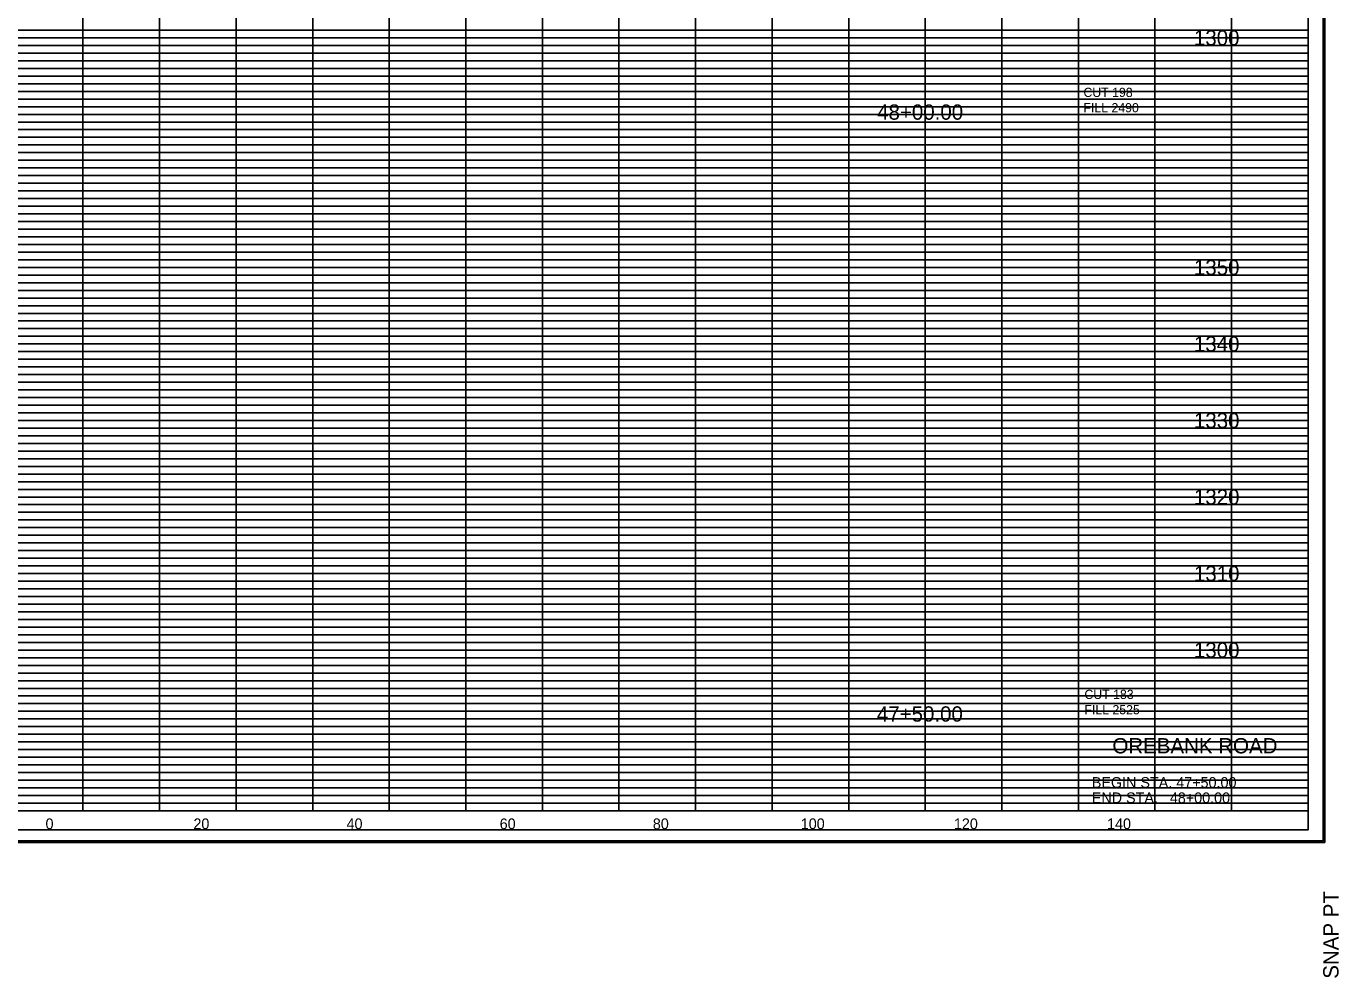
# Model space of a CAD drawing. Extents: x 980 to 1324, y 978 to 2847.
# Drawn here: x 1152.6 to 1324, y 2328.2 to 2452.5 of the extents above; entities that cross this region are included whole.
import ezdxf

# ---------------------------------------------------------------- set-up
doc = ezdxf.new("R2010")
doc.units = 0
for name, color, linetype in [('DESIGN - SHEET - Corner Text', 7, 'Continuous'), ('DESIGN - SHEET - Light Grid', 7, 'Continuous'), ('DESIGN - SHEET - Linework', 7, 'Continuous'), ('DESIGN - SHEET - Plot Shape', 7, 'Continuous'), ('DESIGN - TYPICAL - Text', 7, 'Continuous')]:
    doc.layers.add(name, color=color, linetype=linetype)

# ---------------------------------------------------------------- blocks, each defined once
blk = doc.blocks.new('XSTSHT')
at = {"layer": 'DESIGN - SHEET - Light Grid'}
for p, q in [((8, 10.2), (16, 10.2)), ((16, 10.2), (24, 10.2)), ((24, 10.2), (32, 10.2)), ((8, 10.1), (16, 10.1)), ((16, 10.1), (24, 10.1)), ((24, 10.1), (32, 10.1)), ((8, 9.9), (16, 9.9)), ((8, 9.8), (16, 9.8)), ((16, 9.9), (24, 9.9)), ((16, 9.8), (24, 9.8)), ((24, 9.9), (32, 9.9)), ((24, 9.8), (32, 9.8)), ((8, 9.7), (16, 9.7)), ((8, 9.6), (16, 9.6)), ((16, 9.7), (24, 9.7)), ((16, 9.6), (24, 9.6)), ((24, 9.7), (32, 9.7)), ((24, 9.6), (32, 9.6)), ((8, 9.5), (16, 9.5)), ((16, 9.5), (24, 9.5)), ((24, 9.5), (32, 9.5)), ((8, 9.4), (16, 9.4)), ((8, 9.3), (16, 9.3)), ((16, 9.4), (24, 9.4)), ((16, 9.3), (24, 9.3)), ((24, 9.4), (32, 9.4)), ((24, 9.3), (32, 9.3)), ((8, 9.2), (16, 9.2)), ((8, 9.1), (16, 9.1)), ((16, 9.2), (24, 9.2)), ((16, 9.1), (24, 9.1)), ((24, 9.2), (32, 9.2)), ((24, 9.1), (32, 9.1)), ((8, 8.9), (16, 8.9)), ((8, 8.8), (16, 8.8)), ((16, 8.9), (24, 8.9)), ((16, 8.8), (24, 8.8)), ((24, 8.9), (32, 8.9)), ((24, 8.8), (32, 8.8)), ((8, 8.7), (16, 8.7)), ((8, 8.6), (16, 8.6)), ((16, 8.7), (24, 8.7)), ((16, 8.6), (24, 8.6)), ((24, 8.7), (32, 8.7)), ((24, 8.6), (32, 8.6)), ((8, 8.5), (16, 8.5)), ((8, 8.4), (16, 8.4)), ((16, 8.5), (24, 8.5)), ((16, 8.4), (24, 8.4)), ((24, 8.5), (32, 8.5)), ((24, 8.4), (32, 8.4)), ((8, 8.3), (16, 8.3)), ((16, 8.3), (24, 8.3)), ((24, 8.3), (32, 8.3)), ((8, 8.2), (16, 8.2)), ((8, 8.1), (16, 8.1)), ((16, 8.2), (24, 8.2)), ((16, 8.1), (24, 8.1)), ((24, 8.2), (32, 8.2)), ((24, 8.1), (32, 8.1)), ((8, 7.9), (16, 7.9)), ((16, 7.9), (24, 7.9)), ((24, 7.9), (32, 7.9)), ((8, 7.8), (16, 7.8)), ((16, 7.8), (24, 7.8)), ((24, 7.8), (32, 7.8)), ((8, 7.7), (16, 7.7)), ((8, 7.6), (16, 7.6)), ((16, 7.7), (24, 7.7)), ((16, 7.6), (24, 7.6)), ((24, 7.7), (32, 7.7)), ((24, 7.6), (32, 7.6)), ((8, 7.5), (16, 7.5)), ((8, 7.4), (16, 7.4)), ((16, 7.5), (24, 7.5)), ((16, 7.4), (24, 7.4)), ((24, 7.5), (32, 7.5)), ((24, 7.4), (32, 7.4)), ((8, 7.3), (16, 7.3)), ((8, 7.2), (16, 7.2)), ((16, 7.3), (24, 7.3)), ((16, 7.2), (24, 7.2)), ((24, 7.3), (32, 7.3)), ((24, 7.2), (32, 7.2)), ((8, 7.1), (16, 7.1)), ((16, 7.1), (24, 7.1)), ((24, 7.1), (32, 7.1)), ((8, 6.9), (16, 6.9)), ((16, 6.9), (24, 6.9)), ((24, 6.9), (32, 6.9)), ((8, 6.8), (16, 6.8)), ((8, 6.7), (16, 6.7)), ((16, 6.8), (24, 6.8)), ((16, 6.7), (24, 6.7)), ((24, 6.8), (32, 6.8)), ((24, 6.7), (32, 6.7)), ((8, 6.6), (16, 6.6)), ((16, 6.6), (24, 6.6)), ((24, 6.6), (32, 6.6)), ((8, 6.5), (16, 6.5)), ((8, 6.4), (16, 6.4)), ((16, 6.5), (24, 6.5)), ((16, 6.4), (24, 6.4)), ((24, 6.5), (32, 6.5)), ((24, 6.4), (32, 6.4)), ((8, 6.3), (16, 6.3)), ((8, 6.2), (16, 6.2)), ((16, 6.3), (24, 6.3)), ((16, 6.2), (24, 6.2)), ((24, 6.3), (32, 6.3)), ((24, 6.2), (32, 6.2)), ((8, 6.1), (16, 6.1)), ((16, 6.1), (24, 6.1)), ((24, 6.1), (32, 6.1)), ((8, 5.9), (16, 5.9)), ((16, 5.9), (24, 5.9)), ((24, 5.9), (32, 5.9)), ((8, 5.8), (16, 5.8)), ((8, 5.7), (16, 5.7)), ((16, 5.8), (24, 5.8)), ((16, 5.7), (24, 5.7)), ((24, 5.8), (32, 5.8)), ((24, 5.7), (32, 5.7)), ((8, 5.6), (16, 5.6)), ((8, 5.5), (16, 5.5)), ((16, 5.6), (24, 5.6)), ((16, 5.5), (24, 5.5)), ((24, 5.6), (32, 5.6)), ((24, 5.5), (32, 5.5)), ((8, 5.4), (16, 5.4)), ((16, 5.4), (24, 5.4)), ((24, 5.4), (32, 5.4)), ((8, 5.3), (16, 5.3)), ((8, 5.2), (16, 5.2)), ((16, 5.3), (24, 5.3)), ((16, 5.2), (24, 5.2)), ((24, 5.3), (32, 5.3)), ((24, 5.2), (32, 5.2)), ((8, 5.1), (16, 5.1)), ((16, 5.1), (24, 5.1)), ((24, 5.1), (32, 5.1)), ((8, 4.9), (16, 4.9)), ((8, 4.8), (16, 4.8)), ((16, 4.9), (24, 4.9)), ((16, 4.8), (24, 4.8)), ((24, 4.9), (32, 4.9)), ((24, 4.8), (32, 4.8)), ((8, 4.7), (16, 4.7)), ((16, 4.7), (24, 4.7)), ((24, 4.7), (32, 4.7)), ((8, 4.6), (16, 4.6)), ((8, 4.5), (16, 4.5)), ((16, 4.6), (24, 4.6)), ((16, 4.5), (24, 4.5)), ((24, 4.6), (32, 4.6)), ((24, 4.5), (32, 4.5)), ((8, 4.4), (16, 4.4)), ((8, 4.3), (16, 4.3)), ((16, 4.4), (24, 4.4)), ((16, 4.3), (24, 4.3)), ((24, 4.4), (32, 4.4)), ((24, 4.3), (32, 4.3)), ((8, 4.2), (16, 4.2)), ((16, 4.2), (24, 4.2)), ((24, 4.2), (32, 4.2)), ((8, 4.1), (16, 4.1)), ((16, 4.1), (24, 4.1)), ((24, 4.1), (32, 4.1)), ((8, 3.9), (16, 3.9)), ((8, 3.8), (16, 3.8)), ((16, 3.9), (24, 3.9)), ((16, 3.8), (24, 3.8)), ((24, 3.9), (32, 3.9)), ((24, 3.8), (32, 3.8)), ((8, 3.7), (16, 3.7)), ((8, 3.6), (16, 3.6)), ((16, 3.7), (24, 3.7)), ((16, 3.6), (24, 3.6)), ((24, 3.7), (32, 3.7)), ((24, 3.6), (32, 3.6)), ((8, 3.5), (16, 3.5)), ((16, 3.5), (24, 3.5)), ((24, 3.5), (32, 3.5)), ((8, 3.4), (16, 3.4)), ((8, 3.3), (16, 3.3)), ((16, 3.4), (24, 3.4)), ((16, 3.3), (24, 3.3)), ((24, 3.4), (32, 3.4)), ((24, 3.3), (32, 3.3)), ((8, 3.2), (16, 3.2)), ((8, 3.1), (16, 3.1)), ((16, 3.2), (24, 3.2)), ((16, 3.1), (24, 3.1)), ((24, 3.2), (32, 3.2)), ((24, 3.1), (32, 3.1)), ((8, 2.9), (16, 2.9)), ((8, 2.8), (16, 2.8)), ((16, 2.9), (24, 2.9)), ((16, 2.8), (24, 2.8)), ((24, 2.9), (32, 2.9)), ((24, 2.8), (32, 2.8)), ((8, 2.7), (16, 2.7)), ((8, 2.6), (16, 2.6)), ((16, 2.7), (24, 2.7)), ((16, 2.6), (24, 2.6)), ((24, 2.7), (32, 2.7)), ((24, 2.6), (32, 2.6)), ((8, 2.5), (16, 2.5)), ((8, 2.4), (16, 2.4)), ((16, 2.5), (24, 2.5)), ((16, 2.4), (24, 2.4)), ((24, 2.5), (32, 2.5)), ((24, 2.4), (32, 2.4)), ((8, 2.3), (16, 2.3)), ((16, 2.3), (24, 2.3)), ((24, 2.3), (32, 2.3)), ((8, 2.2), (16, 2.2)), ((8, 2.1), (16, 2.1)), ((16, 2.2), (24, 2.2)), ((16, 2.1), (24, 2.1)), ((24, 2.2), (32, 2.2)), ((24, 2.1), (32, 2.1)), ((8, 1.9), (16, 1.9)), ((16, 1.9), (24, 1.9)), ((24, 1.9), (32, 1.9)), ((8, 1.8), (16, 1.8)), ((16, 1.8), (24, 1.8)), ((24, 1.8), (32, 1.8)), ((8, 1.7), (16, 1.7)), ((8, 1.6), (16, 1.6)), ((16, 1.7), (24, 1.7)), ((16, 1.6), (24, 1.6)), ((24, 1.7), (32, 1.7)), ((24, 1.6), (32, 1.6)), ((8, 1.5), (16, 1.5)), ((8, 1.4), (16, 1.4)), ((16, 1.5), (24, 1.5)), ((16, 1.4), (24, 1.4)), ((24, 1.5), (32, 1.5)), ((24, 1.4), (32, 1.4)), ((8, 1.3), (16, 1.3)), ((8, 1.2), (16, 1.2)), ((16, 1.3), (24, 1.3)), ((16, 1.2), (24, 1.2)), ((24, 1.3), (32, 1.3)), ((24, 1.2), (32, 1.2)), ((8, 1.1), (16, 1.1)), ((16, 1.1), (24, 1.1)), ((24, 1.1), (32, 1.1)), ((8, 0.9), (16, 0.9)), ((16, 0.9), (24, 0.9)), ((24, 0.9), (32, 0.9)), ((8, 0.8), (16, 0.8)), ((8, 0.7), (16, 0.7)), ((16, 0.8), (24, 0.8)), ((16, 0.7), (24, 0.7)), ((24, 0.8), (32, 0.8)), ((24, 0.7), (32, 0.7)), ((8, 0.6), (16, 0.6)), ((16, 0.6), (24, 0.6)), ((24, 0.6), (32, 0.6)), ((8, 0.5), (16, 0.5)), ((8, 0.4), (16, 0.4)), ((16, 0.5), (24, 0.5)), ((16, 0.4), (24, 0.4)), ((24, 0.5), (32, 0.5)), ((24, 0.4), (32, 0.4)), ((8, 0.3), (16, 0.3)), ((8, 0.2), (16, 0.2)), ((16, 0.3), (24, 0.3)), ((16, 0.2), (24, 0.2)), ((24, 0.3), (32, 0.3)), ((24, 0.2), (32, 0.2)), ((8, 0.1), (16, 0.1)), ((16, 0.1), (24, 0.1)), ((24, 0.1), (32, 0.1))]:
    blk.add_line(p, q, dxfattribs=at)
at = {"layer": 'DESIGN - SHEET - Linework'}
for p, q in [((32.217, 21.414), (32.217, -0.414)), ((16, 0), (16, 21)), ((17, 0), (17, 21)), ((18, 0), (18, 21)), ((19, 0), (19, 21)), ((20, 0), (20, 21)), ((21, 0), (21, 21)), ((22, 0), (22, 21)), ((23, 0), (23, 21)), ((24, 0), (24, 21)), ((25, 0), (25, 21)), ((26, 0), (26, 21)), ((27, 0), (27, 21)), ((28, 0), (28, 20)), ((29, 0), (29, 20)), ((30, 0), (30, 20)), ((31, 0), (31, 20)), ((0, 10), (32, 10)), ((0, 9), (32, 9)), ((0, 8), (32, 8)), ((0, 7), (32, 7)), ((0, 6), (32, 6)), ((0, 5), (32, 5)), ((0, 4), (32, 4)), ((0, 3), (32, 3)), ((0, 2), (32, 2)), ((0, 1), (32, 1)), ((-1.823, -0.414), (32.217, -0.414))]:
    blk.add_line(p, q, dxfattribs=at)
blk.add_lwpolyline([(0, 21), (0, 0), (32, 0), (32, 21), (0, 21)], dxfattribs=at)
at = {"layer": 'DESIGN - SHEET - Plot Shape'}
for points in [[(-1.803, 21.394), (32.197, 21.394), (32.197, -0.394), (-1.803, -0.394)], [(-0.85, 21), (32, 21), (32, -0.25), (-0.85, -0.25)]]:
    blk.add_lwpolyline(points, close=True, dxfattribs=at)
at = {"layer": 'DESIGN - SHEET - Corner Text'}
blk.add_text('SNAP PT  ', height=0.2, rotation=90, dxfattribs=at).set_placement((32.397, -2.194))

msp = doc.modelspace()

# ---------------------------------------------------------------- linework, layer by layer
at = {"layer": 'DESIGN - SHEET - Plot Shape'}
msp.add_lwpolyline([(991.5, 2347.5), (1320, 2347.5), (1320, 2560), (991.5, 2560)], close=True, dxfattribs=at)

# ---------------------------------------------------------------- block references
at = {"layer": 'DESIGN - SHEET - Plot Shape', "xscale": 10, "yscale": 10}
msp.add_blockref('XSTSHT', (1000, 2350), dxfattribs=at)

# ---------------------------------------------------------------- texts
at = {"layer": 'DESIGN - SHEET - Corner Text'}
for s, height, p in [('OREBANK ROAD', 2, (1294.44, 2357.5)), ('BEGIN STA. 47+50.00', 1.4, (1291.75, 2353)), ('END STA.   48+00.00', 1.4, (1291.75, 2351))]:
    msp.add_text(s, height=height, dxfattribs=at).set_placement(p)
at = {"layer": 'DESIGN - TYPICAL - Text'}
for s, height, p in [('     1300     ', 2, (1301.37, 2450)), ('CUT 198', 1.2, (1290.66, 2443.27)), ('     48+00.00     ', 2, (1260, 2440.3)), ('FILL 2490', 1.2, (1290.66, 2441.27)), ('     1350     ', 2, (1301.37, 2420)), ('     1340     ', 2, (1301.37, 2410)), ('     1330     ', 2, (1301.37, 2400)), ('     1320     ', 2, (1301.37, 2390)), ('     1310     ', 2, (1301.37, 2380)), ('     1300     ', 2, (1301.37, 2370)), ('CUT 183', 1.2, (1290.79, 2364.61)), ('FILL 2525', 1.2, (1290.79, 2362.61)), ('     47+50.00     ', 2, (1259.96, 2361.65)), ('     0     ', 1.4, (1152.51, 2347.6)), ('     0     ', 1.4, (1152.51, 2347.6)), ('     20     ', 1.4, (1171.82, 2347.6)), ('     40     ', 1.4, (1191.82, 2347.6)), ('     60     ', 1.4, (1211.82, 2347.6)), ('     80     ', 1.4, (1231.82, 2347.6)), ('     100     ', 1.4, (1251.14, 2347.6)), ('     120     ', 1.4, (1271.14, 2347.6)), ('     140     ', 1.4, (1291.14, 2347.6))]:
    msp.add_text(s, height=height, dxfattribs=at).set_placement(p)

doc.saveas('drawing.dxf')
